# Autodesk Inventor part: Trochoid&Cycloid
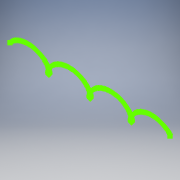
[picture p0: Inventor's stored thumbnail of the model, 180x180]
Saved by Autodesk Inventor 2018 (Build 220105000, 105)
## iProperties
Created: 2008-02
Part Number: Trochoid&Cycloid
Document SubType Name: Modeling
Designer: Autodesk, Inc.
Density: 1 g/cm^3
Material: Generic
Appearance: Default
Author: Autodesk, Inc.
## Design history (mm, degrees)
sketch "Sketch1"
  geometry: 300 further points
  constraints: 300 other
